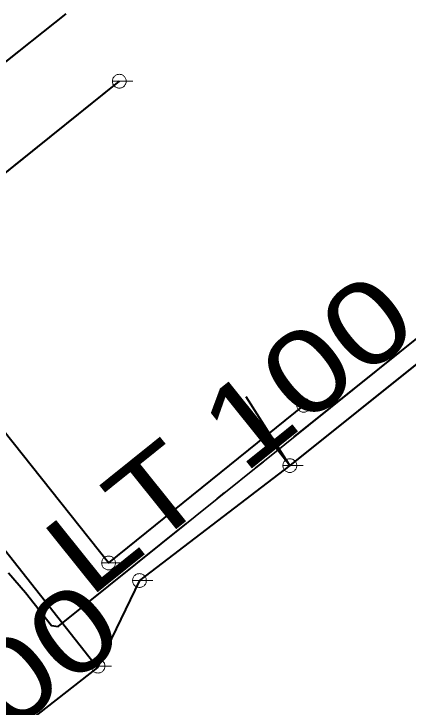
# Model space of a CAD drawing. Extents: x -968691 to -140888, y -1376050 to -879856.
# Drawn here: x -647897.4 to -647839.9, y -1058985.7 to -1058884.6 of the extents above; entities that cross this region are included whole.
import ezdxf
from ezdxf.enums import TextEntityAlignment as Align

# ---------------------------------------------------------------- set-up
doc = ezdxf.new("R2010")
doc.units = 0
doc.header["$LTSCALE"] = 4.8
doc.linetypes.add('DASH_DOUBLE_DOT', pattern=[9.2, 5, -1.2, 0.3, -1.2, 0.3, -1.2])
doc.linetypes.add('LONG_DASHED', pattern=[7.5, 6, -1.5])
doc.layers.add('1', color=7, linetype='Continuous', lineweight=13)

msp = doc.modelspace()

# ---------------------------------------------------------------- linework, layer by layer
at = {"layer": '1', "lineweight": 40}
for p, q in [((-647889.855, -1058884.56), (-647919.323, -1058907.958)), ((-647882.046, -1058894.386), (-647911.447, -1058917.978)), ((-647836.069, -1058933.571), (-647857.153, -1058950.476)), ((-647857.153, -1058950.476), (-647879.103, -1058967.253)), ((-647879.103, -1058967.253), (-647885.22, -1058979.927))]:
    msp.add_line(p, q, dxfattribs=at)
at = {"layer": '1', "lineweight": 35}
for p, q in [((-647889.855, -1058884.56), (-647919.323, -1058907.958)), ((-647882.046, -1058894.386), (-647911.447, -1058917.978)), ((-647836.069, -1058933.571), (-647857.153, -1058950.476)), ((-647857.153, -1058950.476), (-647879.103, -1058967.253)), ((-647879.103, -1058967.253), (-647885.22, -1058979.927))]:
    msp.add_line(p, q, dxfattribs=at)
at = {"layer": '1'}
for p, q in [((-647883.054, -1058894.386), (-647880.077, -1058894.386)), ((-647857.692, -1058949.634), (-647863.55, -1058940.466)), ((-647857.765, -1058949.686), (-647864.431, -1058941.104)), ((-647856.138, -1058941.677), (-647853.161, -1058941.677)), ((-647857.153, -1058950.476), (-647857.765, -1058949.686)), ((-647857.153, -1058950.476), (-647857.692, -1058949.634)), ((-647858.161, -1058950.476), (-647855.185, -1058950.476)), ((-647884.619, -1058964.687), (-647881.642, -1058964.687)), ((-647880.111, -1058967.253), (-647877.135, -1058967.253)), ((-647886.157, -1058979.739), (-647883.181, -1058979.739))]:
    msp.add_line(p, q, dxfattribs=at)
at = {"layer": '1', "linetype": 'LONG_DASHED', "lineweight": 40}
for p, q in [((-647857.692, -1058949.634), (-647863.55, -1058940.466)), ((-647857.765, -1058949.686), (-647864.431, -1058941.104)), ((-647857.153, -1058950.476), (-647857.765, -1058949.686)), ((-647857.153, -1058950.476), (-647857.692, -1058949.634))]:
    msp.add_line(p, q, dxfattribs=at)
at = {"layer": '1'}
for points in [[(-647882.046, -1058893.378), (-647882.151, -1058893.384), (-647882.255, -1058893.4), (-647882.357, -1058893.427), (-647882.455, -1058893.465), (-647882.549, -1058893.513), (-647882.637, -1058893.57), (-647882.72, -1058893.637), (-647882.795, -1058893.712), (-647882.861, -1058893.794), (-647882.918, -1058893.881), (-647882.965, -1058893.976), (-647883.003, -1058894.075), (-647883.031, -1058894.176), (-647883.047, -1058894.281), (-647883.054, -1058894.386), (-647883.047, -1058894.491), (-647883.031, -1058894.596), (-647883.003, -1058894.698), (-647882.965, -1058894.796), (-647882.918, -1058894.889), (-647882.861, -1058894.979), (-647882.795, -1058895.061), (-647882.72, -1058895.135), (-647882.637, -1058895.201), (-647882.549, -1058895.259), (-647882.455, -1058895.307), (-647882.357, -1058895.345), (-647882.255, -1058895.372), (-647882.151, -1058895.388), (-647882.046, -1058895.394), (-647881.94, -1058895.388), (-647881.835, -1058895.372), (-647881.734, -1058895.345), (-647881.636, -1058895.307), (-647881.541, -1058895.259), (-647881.453, -1058895.201), (-647881.371, -1058895.135), (-647881.296, -1058895.061), (-647881.23, -1058894.979), (-647881.173, -1058894.889), (-647881.124, -1058894.796), (-647881.086, -1058894.698), (-647881.06, -1058894.596), (-647881.044, -1058894.491), (-647881.038, -1058894.386), (-647881.044, -1058894.281), (-647881.06, -1058894.176), (-647881.086, -1058894.075), (-647881.124, -1058893.976), (-647881.173, -1058893.881), (-647881.23, -1058893.794), (-647881.296, -1058893.712), (-647881.371, -1058893.637), (-647881.453, -1058893.57), (-647881.541, -1058893.513), (-647881.636, -1058893.465), (-647881.734, -1058893.427), (-647881.835, -1058893.4), (-647881.94, -1058893.384)], [(-647855.13, -1058940.669), (-647855.235, -1058940.675), (-647855.339, -1058940.691), (-647855.441, -1058940.718), (-647855.539, -1058940.756), (-647855.633, -1058940.804), (-647855.721, -1058940.861), (-647855.804, -1058940.928), (-647855.879, -1058941.003), (-647855.945, -1058941.085), (-647856.002, -1058941.172), (-647856.049, -1058941.267), (-647856.087, -1058941.366), (-647856.115, -1058941.467), (-647856.131, -1058941.572), (-647856.138, -1058941.677), (-647856.131, -1058941.782), (-647856.115, -1058941.887), (-647856.087, -1058941.989), (-647856.049, -1058942.087), (-647856.002, -1058942.18), (-647855.945, -1058942.27), (-647855.879, -1058942.352), (-647855.804, -1058942.426), (-647855.721, -1058942.492), (-647855.633, -1058942.55), (-647855.539, -1058942.598), (-647855.441, -1058942.636), (-647855.339, -1058942.663), (-647855.235, -1058942.679), (-647855.13, -1058942.685), (-647855.024, -1058942.679), (-647854.919, -1058942.663), (-647854.818, -1058942.636), (-647854.72, -1058942.598), (-647854.625, -1058942.55), (-647854.537, -1058942.492), (-647854.455, -1058942.426), (-647854.38, -1058942.352), (-647854.314, -1058942.27), (-647854.257, -1058942.18), (-647854.208, -1058942.087), (-647854.17, -1058941.989), (-647854.144, -1058941.887), (-647854.128, -1058941.782), (-647854.122, -1058941.677), (-647854.128, -1058941.572), (-647854.144, -1058941.467), (-647854.17, -1058941.366), (-647854.208, -1058941.267), (-647854.257, -1058941.172), (-647854.314, -1058941.085), (-647854.38, -1058941.003), (-647854.455, -1058940.928), (-647854.537, -1058940.861), (-647854.625, -1058940.804), (-647854.72, -1058940.756), (-647854.818, -1058940.718), (-647854.919, -1058940.691), (-647855.024, -1058940.675)], [(-647857.153, -1058949.468), (-647857.258, -1058949.474), (-647857.362, -1058949.49), (-647857.464, -1058949.518), (-647857.563, -1058949.556), (-647857.657, -1058949.603), (-647857.745, -1058949.661), (-647857.827, -1058949.727), (-647857.902, -1058949.802), (-647857.968, -1058949.884), (-647858.026, -1058949.972), (-647858.073, -1058950.066), (-647858.111, -1058950.165), (-647858.139, -1058950.267), (-647858.155, -1058950.371), (-647858.161, -1058950.476), (-647858.155, -1058950.581), (-647858.139, -1058950.686), (-647858.111, -1058950.788), (-647858.073, -1058950.886), (-647858.026, -1058950.98), (-647857.968, -1058951.069), (-647857.902, -1058951.151), (-647857.827, -1058951.225), (-647857.745, -1058951.291), (-647857.657, -1058951.349), (-647857.563, -1058951.397), (-647857.464, -1058951.435), (-647857.362, -1058951.462), (-647857.258, -1058951.478), (-647857.153, -1058951.484), (-647857.048, -1058951.478), (-647856.943, -1058951.462), (-647856.841, -1058951.435), (-647856.743, -1058951.397), (-647856.649, -1058951.349), (-647856.56, -1058951.291), (-647856.478, -1058951.225), (-647856.404, -1058951.151), (-647856.338, -1058951.069), (-647856.28, -1058950.98), (-647856.232, -1058950.886), (-647856.194, -1058950.788), (-647856.167, -1058950.686), (-647856.151, -1058950.581), (-647856.145, -1058950.476), (-647856.151, -1058950.371), (-647856.167, -1058950.267), (-647856.194, -1058950.165), (-647856.232, -1058950.066), (-647856.28, -1058949.972), (-647856.338, -1058949.884), (-647856.404, -1058949.802), (-647856.478, -1058949.727), (-647856.56, -1058949.661), (-647856.649, -1058949.603), (-647856.743, -1058949.556), (-647856.841, -1058949.518), (-647856.943, -1058949.49), (-647857.048, -1058949.474)], [(-647883.611, -1058963.679), (-647883.716, -1058963.685), (-647883.82, -1058963.701), (-647883.922, -1058963.728), (-647884.02, -1058963.766), (-647884.114, -1058963.814), (-647884.202, -1058963.871), (-647884.285, -1058963.938), (-647884.36, -1058964.013), (-647884.426, -1058964.095), (-647884.483, -1058964.182), (-647884.53, -1058964.277), (-647884.568, -1058964.376), (-647884.596, -1058964.477), (-647884.612, -1058964.582), (-647884.619, -1058964.687), (-647884.612, -1058964.792), (-647884.596, -1058964.897), (-647884.568, -1058964.999), (-647884.53, -1058965.097), (-647884.483, -1058965.19), (-647884.426, -1058965.28), (-647884.36, -1058965.362), (-647884.285, -1058965.436), (-647884.202, -1058965.502), (-647884.114, -1058965.56), (-647884.02, -1058965.608), (-647883.922, -1058965.646), (-647883.82, -1058965.673), (-647883.716, -1058965.689), (-647883.611, -1058965.695), (-647883.505, -1058965.689), (-647883.4, -1058965.673), (-647883.299, -1058965.646), (-647883.201, -1058965.608), (-647883.106, -1058965.56), (-647883.018, -1058965.502), (-647882.936, -1058965.436), (-647882.861, -1058965.362), (-647882.795, -1058965.28), (-647882.738, -1058965.19), (-647882.689, -1058965.097), (-647882.651, -1058964.999), (-647882.625, -1058964.897), (-647882.609, -1058964.792), (-647882.603, -1058964.687), (-647882.609, -1058964.582), (-647882.625, -1058964.477), (-647882.651, -1058964.376), (-647882.689, -1058964.277), (-647882.738, -1058964.182), (-647882.795, -1058964.095), (-647882.861, -1058964.013), (-647882.936, -1058963.938), (-647883.018, -1058963.871), (-647883.106, -1058963.814), (-647883.201, -1058963.766), (-647883.299, -1058963.728), (-647883.4, -1058963.701), (-647883.505, -1058963.685)], [(-647879.103, -1058966.245), (-647879.208, -1058966.251), (-647879.312, -1058966.267), (-647879.414, -1058966.295), (-647879.513, -1058966.333), (-647879.607, -1058966.38), (-647879.695, -1058966.438), (-647879.777, -1058966.504), (-647879.852, -1058966.579), (-647879.918, -1058966.661), (-647879.976, -1058966.749), (-647880.023, -1058966.843), (-647880.061, -1058966.942), (-647880.089, -1058967.044), (-647880.105, -1058967.148), (-647880.111, -1058967.253), (-647880.105, -1058967.358), (-647880.089, -1058967.463), (-647880.061, -1058967.565), (-647880.023, -1058967.663), (-647879.976, -1058967.757), (-647879.918, -1058967.846), (-647879.852, -1058967.928), (-647879.777, -1058968.002), (-647879.695, -1058968.068), (-647879.607, -1058968.126), (-647879.513, -1058968.174), (-647879.414, -1058968.212), (-647879.312, -1058968.239), (-647879.208, -1058968.255), (-647879.103, -1058968.261), (-647878.998, -1058968.255), (-647878.893, -1058968.239), (-647878.791, -1058968.212), (-647878.693, -1058968.174), (-647878.599, -1058968.126), (-647878.51, -1058968.068), (-647878.428, -1058968.002), (-647878.354, -1058967.928), (-647878.288, -1058967.846), (-647878.23, -1058967.757), (-647878.182, -1058967.663), (-647878.144, -1058967.565), (-647878.117, -1058967.463), (-647878.101, -1058967.358), (-647878.095, -1058967.253), (-647878.101, -1058967.148), (-647878.117, -1058967.044), (-647878.144, -1058966.942), (-647878.182, -1058966.843), (-647878.23, -1058966.749), (-647878.288, -1058966.661), (-647878.354, -1058966.579), (-647878.428, -1058966.504), (-647878.51, -1058966.438), (-647878.599, -1058966.38), (-647878.693, -1058966.333), (-647878.791, -1058966.295), (-647878.893, -1058966.267), (-647878.998, -1058966.251)], [(-647885.149, -1058978.731), (-647885.254, -1058978.737), (-647885.358, -1058978.753), (-647885.46, -1058978.781), (-647885.559, -1058978.819), (-647885.653, -1058978.866), (-647885.741, -1058978.924), (-647885.823, -1058978.99), (-647885.898, -1058979.065), (-647885.964, -1058979.147), (-647886.022, -1058979.235), (-647886.069, -1058979.329), (-647886.107, -1058979.428), (-647886.135, -1058979.53), (-647886.151, -1058979.634), (-647886.157, -1058979.739), (-647886.151, -1058979.844), (-647886.135, -1058979.949), (-647886.107, -1058980.051), (-647886.069, -1058980.149), (-647886.022, -1058980.243), (-647885.964, -1058980.332), (-647885.898, -1058980.414), (-647885.823, -1058980.488), (-647885.741, -1058980.554), (-647885.653, -1058980.612), (-647885.559, -1058980.66), (-647885.46, -1058980.698), (-647885.358, -1058980.725), (-647885.254, -1058980.741), (-647885.149, -1058980.747), (-647885.044, -1058980.741), (-647884.939, -1058980.725), (-647884.837, -1058980.698), (-647884.739, -1058980.66), (-647884.645, -1058980.612), (-647884.556, -1058980.554), (-647884.474, -1058980.488), (-647884.4, -1058980.414), (-647884.334, -1058980.332), (-647884.276, -1058980.243), (-647884.228, -1058980.149), (-647884.19, -1058980.051), (-647884.163, -1058979.949), (-647884.147, -1058979.844), (-647884.141, -1058979.739), (-647884.147, -1058979.634), (-647884.163, -1058979.53), (-647884.19, -1058979.428), (-647884.228, -1058979.329), (-647884.276, -1058979.235), (-647884.334, -1058979.147), (-647884.4, -1058979.065), (-647884.474, -1058978.99), (-647884.556, -1058978.924), (-647884.645, -1058978.866), (-647884.739, -1058978.819), (-647884.837, -1058978.781), (-647884.939, -1058978.753), (-647885.044, -1058978.737)]]:
    msp.add_lwpolyline(points, close=True, dxfattribs=at)
at = {"layer": '1', "linetype": 'DASH_DOUBLE_DOT', "lineweight": 40}
msp.add_lwpolyline([(-647898.218, -1058966.118), (-647895.751, -1058968.98), (-647891.96, -1058973.83), (-647890.95, -1058973.95), (-647837.9, -1058931.36), (-647796.809, -1058898.408)], dxfattribs=at)
at = {"layer": '1', "lineweight": 35}
for points in [[(-647898.218, -1058966.118), (-647895.751, -1058968.98), (-647891.96, -1058973.83), (-647890.95, -1058973.95), (-647837.9, -1058931.36), (-647796.809, -1058898.408)], [(-647855.13, -1058941.677), (-647883.611, -1058964.687), (-647917.138, -1058922.546)], [(-647915.525, -1058942.102), (-647902.625, -1058957.89), (-647885.22, -1058979.927), (-647932.41, -1059016.786)]]:
    msp.add_lwpolyline(points, dxfattribs=at)
at = {"layer": '1', "lineweight": 40}
for points in [[(-647855.13, -1058941.677), (-647883.611, -1058964.687), (-647917.138, -1058922.546)], [(-647915.525, -1058942.102), (-647902.625, -1058957.89), (-647885.22, -1058979.927), (-647932.41, -1059016.786)]]:
    msp.add_lwpolyline(points, dxfattribs=at)

# ---------------------------------------------------------------- texts
at = {"layer": '1', "width": 1.25}
for s, rotation, p in [('LT 100', 38.758, (-647862.147, -1058950.441)), ('PP 400', 37.993, (-647906.576, -1058996.227))]:
    msp.add_text(s, height=12, rotation=rotation, dxfattribs=at).set_placement(p, align=Align.CENTER)

doc.saveas('drawing.dxf')
